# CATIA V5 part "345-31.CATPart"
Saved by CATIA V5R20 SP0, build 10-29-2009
Part number: 345-31
Definition: NONE
Nomenclature: 345-31
Source: Unknown
Description: 345-31
Bounding box of the stored display mesh (mm): x 0 to 72, y -36 to 36, z -36 to 36
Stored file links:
  C:\Users\Utente\Desktop\IO LAVORO\3D X SITO CF\X SITO\345-346\345-31.CATPart
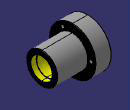
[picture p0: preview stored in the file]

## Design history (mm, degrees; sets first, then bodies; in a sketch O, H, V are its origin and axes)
Body1 "345-31" (main body)
  Solid1: solid without history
